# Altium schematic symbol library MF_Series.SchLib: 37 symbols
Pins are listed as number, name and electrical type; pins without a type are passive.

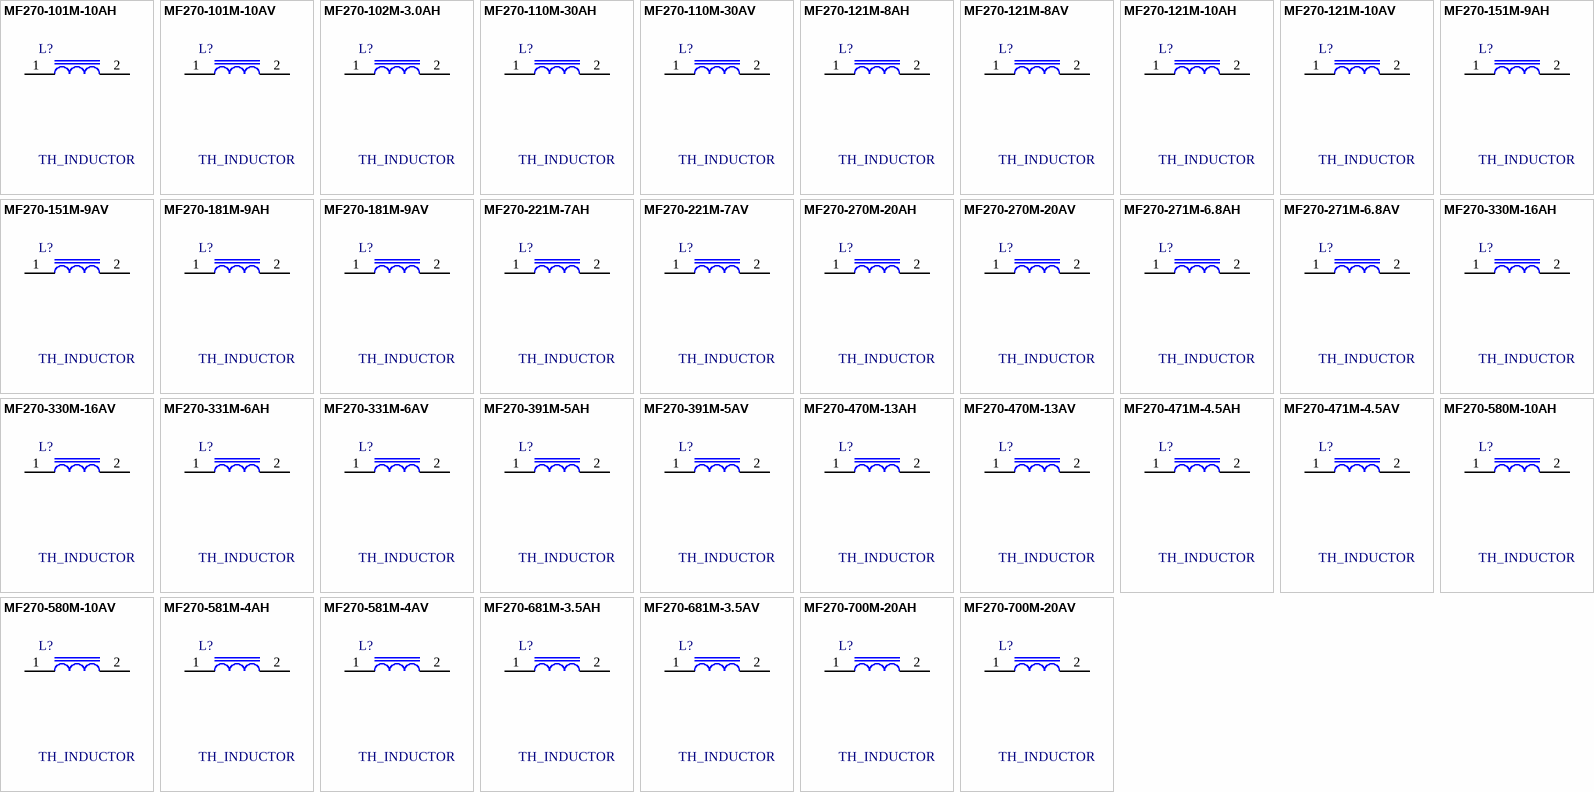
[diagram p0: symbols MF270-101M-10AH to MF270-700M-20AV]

## MF270-101M-10AH
designator L?, comment TH_INDUCTOR
POWER INDUCTOR 10 A, 100 uH, 0.023 mOhms, OD 33.02 mm, HT 25.4 mm; Manufacturer #1: CWS; Sim.Analog.Prefix: L; Sim.Analog.Order: Model$; Current: 10 A; Inductance: 100 uH
footprint MF270-101M-10AH
pins: 1, 2

## MF270-101M-10AV
designator L?, comment TH_INDUCTOR
POWER INDUCTOR 10 A, 100 uH, 0.023 mOhms, OD 33.02 mm, HT 25.4 mm; Manufacturer #1: CWS; Sim.Analog.Prefix: L; Sim.Analog.Order: Model$; Current: 10 A; Inductance: 100 uH
footprint MF270-101M-10AV
pins: 1, 2

## MF270-102M-3.0AH
designator L?, comment TH_INDUCTOR
POWER INDUCTOR 3 A, 1000 uH, 0.25 mOhms, OD 32.51 mm, HT 30.48 mm; Manufacturer #1: CWS; Sim.Analog.Prefix: L; Sim.Analog.Order: Model$; Current: 3 A; Inductance: 1000 uH
footprint MF270-102M-3.0AH
pins: 1, 2

## MF270-110M-30AH
designator L?, comment TH_INDUCTOR
POWER INDUCTOR 30 A, 10.8 uH, 0.004 mOhms, OD 35 mm, HT 25.4 mm; Manufacturer #1: CWS; Sim.Analog.Prefix: L; Sim.Analog.Order: Model$; OD: 35 mm; Current: 30 A; Inductance: 10.8 uH
footprint MF270-110M-30AH
pins: 1, 2

## MF270-110M-30AV
designator L?, comment TH_INDUCTOR
POWER INDUCTOR 30 A, 10.8 uH, 0.004 mOhms, OD 35 mm, HT 25.91 mm; Manufacturer #1: CWS; Sim.Analog.Prefix: L; Sim.Analog.Order: Model$; OD: 35 mm; Current: 30 A; Inductance: 10.8 uH
footprint MF270-110M-30AV
pins: 1, 2

## MF270-121M-8AH
designator L?, comment TH_INDUCTOR
POWER INDUCTOR 8 A, 120 uH, 0.04 mOhms, OD 35 mm, HT 25.4 mm; Manufacturer #1: CWS; Sim.Analog.Prefix: L; Sim.Analog.Order: Model$; OD: 35 mm; Current: 8 A; Inductance: 120 uH
footprint MF270-121M-8AH
pins: 1, 2

## MF270-121M-8AV
designator L?, comment TH_INDUCTOR
POWER INDUCTOR 8 A, 120 uH, 0.04 mOhms, OD 35 mm, HT 25.4 mm; Manufacturer #1: CWS; Sim.Analog.Prefix: L; Sim.Analog.Order: Model$; OD: 35 mm; Current: 8 A; Inductance: 120 uH
footprint MF270-121M-8AV
pins: 1, 2

## MF270-121M-10AH
designator L?, comment TH_INDUCTOR
POWER INDUCTOR 10 A, 120 uH, 0.023 mOhms, OD 33.02 mm, HT 27.18 mm; Manufacturer #1: CWS; Sim.Analog.Prefix: L; Sim.Analog.Order: Model$; Current: 10 A; Inductance: 120 uH
footprint MF270-121M-10AH
pins: 1, 2

## MF270-121M-10AV
designator L?, comment TH_INDUCTOR
POWER INDUCTOR 10 A, 120 uH, 0.023 mOhms, OD 33.02 mm, HT 27.18 mm; Manufacturer #1: CWS; Sim.Analog.Prefix: L; Sim.Analog.Order: Model$; Current: 10 A; Inductance: 120 uH
footprint MF270-121M-10AV
pins: 1, 2

## MF270-151M-9AH
designator L?, comment TH_INDUCTOR
POWER INDUCTOR 9 A, 150 uH, 0.035 mOhms, OD 34.29 mm, HT 33.78 mm; Manufacturer #1: CWS; Sim.Analog.Prefix: L; Sim.Analog.Order: Model$; Current: 9 A; Inductance: 150 uH
footprint MF270-151M-9AH
pins: 1, 2

## MF270-151M-9AV
designator L?, comment TH_INDUCTOR
POWER INDUCTOR 9 A, 150 uH, 0.035 mOhms, OD 34.29 mm, HT 33.53 mm; Manufacturer #1: CWS; Sim.Analog.Prefix: L; Sim.Analog.Order: Model$; Current: 9 A; Inductance: 150 uH
footprint MF270-151M-9AV
pins: 1, 2

## MF270-181M-9AH
designator L?, comment TH_INDUCTOR
POWER INDUCTOR 9 A, 180 uH, 0.035 mOhms, OD 34.29 mm, HT 30.48 mm; Manufacturer #1: CWS; Sim.Analog.Prefix: L; Sim.Analog.Order: Model$; Current: 9 A; Inductance: 180 uH
footprint MF270-181M-9AH
pins: 1, 2

## MF270-181M-9AV
designator L?, comment TH_INDUCTOR
POWER INDUCTOR 9 A, 180 uH, 0.035 mOhms, OD 34.29 mm, HT 30.48 mm; Manufacturer #1: CWS; Sim.Analog.Prefix: L; Sim.Analog.Order: Model$; Current: 9 A; Inductance: 180 uH
footprint MF270-181M-9AV
pins: 1, 2

## MF270-221M-7AH
designator L?, comment TH_INDUCTOR
POWER INDUCTOR 7 A, 220 uH, 0.048 mOhms, OD 33.02 mm, HT 22.2 mm; Manufacturer #1: CWS; Sim.Analog.Prefix: L; Sim.Analog.Order: Model$; Current: 7 A; Inductance: 220 uH
footprint MF270-221M-7AH
pins: 1, 2

## MF270-221M-7AV
designator L?, comment TH_INDUCTOR
POWER INDUCTOR 7 A, 220 uH, 0.048 mOhms, OD 33.02 mm, HT 22.1 mm; Manufacturer #1: CWS; Sim.Analog.Prefix: L; Sim.Analog.Order: Model$; Current: 7 A; Inductance: 220 uH
footprint MF270-221M-7AV
pins: 1, 2

## MF270-270M-20AH
designator L?, comment TH_INDUCTOR
POWER INDUCTOR 20 A, 27 uH, 0.008 mOhms, OD 33.02 mm, HT 25.91 mm; Manufacturer #1: CWS; Sim.Analog.Prefix: L; Sim.Analog.Order: Model$; Current: 20 A; Inductance: 27 uH
footprint MF270-270M-20AH
pins: 1, 2

## MF270-270M-20AV
designator L?, comment TH_INDUCTOR
POWER INDUCTOR 20 A, 27 uH, 0.008 mOhms, OD 33.02 mm, HT 26.67 mm; Manufacturer #1: CWS; Sim.Analog.Prefix: L; Sim.Analog.Order: Model$; Current: 20 A; Inductance: 27 uH
footprint MF270-270M-20AV
pins: 1, 2

## MF270-271M-6.8AH
designator L?, comment TH_INDUCTOR
POWER INDUCTOR 6.8 A, 270 uH, 0.058 mOhms, OD 34.29 mm, HT 22.1 mm; Manufacturer #1: CWS; Sim.Analog.Prefix: L; Sim.Analog.Order: Model$; Current: 6.8 A; Inductance: 270 uH
footprint MF270-271M-6.8AH
pins: 1, 2

## MF270-271M-6.8AV
designator L?, comment TH_INDUCTOR
POWER INDUCTOR 6.8 A, 270 uH, 0.058 mOhms, OD 34.29 mm, HT 18.29 mm; Manufacturer #1: CWS; Sim.Analog.Prefix: L; Sim.Analog.Order: Model$; Current: 6.8 A; Inductance: 270 uH
footprint MF270-271M-6.8AV
pins: 1, 2

## MF270-330M-16AH
designator L?, comment TH_INDUCTOR
POWER INDUCTOR 16 A, 33 uH, 0.01 mOhms, OD 33.02 mm, HT 26.67 mm; Manufacturer #1: CWS; Sim.Analog.Prefix: L; Sim.Analog.Order: Model$; Current: 16 A; Inductance: 33 uH
footprint MF270-330M-16AH
pins: 1, 2

## MF270-330M-16AV
designator L?, comment TH_INDUCTOR
POWER INDUCTOR 16 A, 33 uH, 0.01 mOhms, OD 33.02 mm, HT 25.4 mm; Manufacturer #1: CWS; Sim.Analog.Prefix: L; Sim.Analog.Order: Model$; Current: 16 A; Inductance: 33 uH
footprint MF270-330M-16AV
pins: 1, 2

## MF270-331M-6AH
designator L?, comment TH_INDUCTOR
POWER INDUCTOR 6 A, 330 uH, 0.07 mOhms, OD 34.29 mm, HT 20.57 mm; Manufacturer #1: CWS; Sim.Analog.Prefix: L; Sim.Analog.Order: Model$; Current: 6 A; Inductance: 330 uH
footprint MF270-331M-6AH
pins: 1, 2

## MF270-331M-6AV
designator L?, comment TH_INDUCTOR
POWER INDUCTOR 6 A, 330 uH, 0.07 mOhms, OD 34.29 mm, HT 27.69 mm; Manufacturer #1: CWS; Sim.Analog.Prefix: L; Sim.Analog.Order: Model$; Current: 6 A; Inductance: 330 uH
footprint MF270-331M-6AV
pins: 1, 2

## MF270-391M-5AH
designator L?, comment TH_INDUCTOR
POWER INDUCTOR 5 A, 390 uH, 0.08 mOhms, OD 33.02 mm, HT 16.51 mm; Manufacturer #1: CWS; Sim.Analog.Prefix: L; Sim.Analog.Order: Model$; Current: 5 A; Inductance: 390 uH
footprint MF270-391M-5AH
pins: 1, 2

## MF270-391M-5AV
designator L?, comment TH_INDUCTOR
POWER INDUCTOR 5 A, 390 uH, 0.08 mOhms, OD 33.02 mm, HT 16.51 mm; Manufacturer #1: CWS; Sim.Analog.Prefix: L; Sim.Analog.Order: Model$; Current: 5 A; Inductance: 390 uH
footprint MF270-391M-5AV
pins: 1, 2

## MF270-470M-13AH
designator L?, comment TH_INDUCTOR
POWER INDUCTOR 13 A, 47 uH, 0.015 mOhms, OD 33.02 mm, HT 25.4 mm; Manufacturer #1: CWS; Sim.Analog.Prefix: L; Sim.Analog.Order: Model$; Current: 13 A; Inductance: 47 uH
footprint MF270-470M-13AH
pins: 1, 2

## MF270-470M-13AV
designator L?, comment TH_INDUCTOR
POWER INDUCTOR 13 A, 47 uH, 0.015 mOhms, OD 33.02 mm, HT 50.55 mm; Manufacturer #1: CWS; Sim.Analog.Prefix: L; Sim.Analog.Order: Model$; Current: 13 A; Inductance: 47 uH
footprint MF270-470M-13AV
pins: 1, 2

## MF270-471M-4.5AH
designator L?, comment TH_INDUCTOR
POWER INDUCTOR 4.5 A, 470 uH, 0.1 mOhms, OD 33.02 mm, HT 25.4 mm; Manufacturer #1: CWS; Sim.Analog.Prefix: L; Sim.Analog.Order: Model$; Current: 4.5 A; Inductance: 470 uH
footprint MF270-471M-4.5AH
pins: 1, 2

## MF270-471M-4.5AV
designator L?, comment TH_INDUCTOR
POWER INDUCTOR 4.5 A, 470 uH, 0.1 mOhms, OD 33.02 mm, HT 25.4 mm; Manufacturer #1: CWS; Sim.Analog.Prefix: L; Sim.Analog.Order: Model$; Current: 4.5 A; Inductance: 470 uH
footprint MF270-471M-4.5AV
pins: 1, 2

## MF270-580M-10AH
designator L?, comment TH_INDUCTOR
POWER INDUCTOR 10 A, 58 uH, 0.02 mOhms, OD 33.02 mm, HT 51.82 mm; Manufacturer #1: CWS; Sim.Analog.Prefix: L; Sim.Analog.Order: Model$; Current: 10 A; Inductance: 58 uH
footprint MF270-580M-10AH
pins: 1, 2

## MF270-580M-10AV
designator L?, comment TH_INDUCTOR
POWER INDUCTOR 10 A, 58 uH, 0.02 mOhms, OD 33.02 mm, HT 27.43 mm; Manufacturer #1: CWS; Sim.Analog.Prefix: L; Sim.Analog.Order: Model$; Current: 10 A; Inductance: 58 uH
footprint MF270-580M-10AV
pins: 1, 2

## MF270-581M-4AH
designator L?, comment TH_INDUCTOR
POWER INDUCTOR 4 A, 580 uH, 0.15 mOhms, OD 33.02 mm, HT 27.69 mm; Manufacturer #1: CWS; Sim.Analog.Prefix: L; Sim.Analog.Order: Model$; Current: 4 A; Inductance: 580 uH
footprint MF270-581M-4AH
pins: 1, 2

## MF270-581M-4AV
designator L?, comment TH_INDUCTOR
POWER INDUCTOR 4 A, 580 uH, 0.15 mOhms, OD 33.02 mm, HT 33.02 mm; Manufacturer #1: CWS; Sim.Analog.Prefix: L; Sim.Analog.Order: Model$; Current: 4 A; Inductance: 580 uH
footprint MF270-581M-4AV
pins: 1, 2

## MF270-681M-3.5AH
designator L?, comment TH_INDUCTOR
POWER INDUCTOR 3.5 A, 680 uH, 0.18 mOhms, OD 33.02 mm, HT 33.02 mm; Manufacturer #1: CWS; Sim.Analog.Prefix: L; Sim.Analog.Order: Model$; Current: 3.5 A; Inductance: 680 uH
footprint MF270-681M-3.5AH
pins: 1, 2

## MF270-681M-3.5AV
designator L?, comment TH_INDUCTOR
POWER INDUCTOR 3.5 A, 680 uH, 0.18 mOhms, OD 33.02 mm, HT 30.48 mm; Manufacturer #1: CWS; Sim.Analog.Prefix: L; Sim.Analog.Order: Model$; Current: 3.5 A; Inductance: 680 uH
footprint MF270-681M-3.5AV
pins: 1, 2

## MF270-700M-20AH
designator L?, comment TH_INDUCTOR
POWER INDUCTOR 20 A, 70 uH, 0.008 mOhms, OD 34.93 mm, HT 26.16 mm; Manufacturer #1: CWS; Sim.Analog.Prefix: L; Sim.Analog.Order: Model$; Current: 20 A; Inductance: 70 uH
footprint MF270-700M-20AH
pins: 1, 2

## MF270-700M-20AV
designator L?, comment TH_INDUCTOR
POWER INDUCTOR 10 A, 70 uH, 0.02 mOhms, OD 34.93 mm, HT 26.06 mm; Manufacturer #1: CWS; Sim.Analog.Prefix: L; Sim.Analog.Order: Model$; Current: 10 A; Inductance: 70 uH
footprint MF270-700M-20AV
pins: 1, 2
